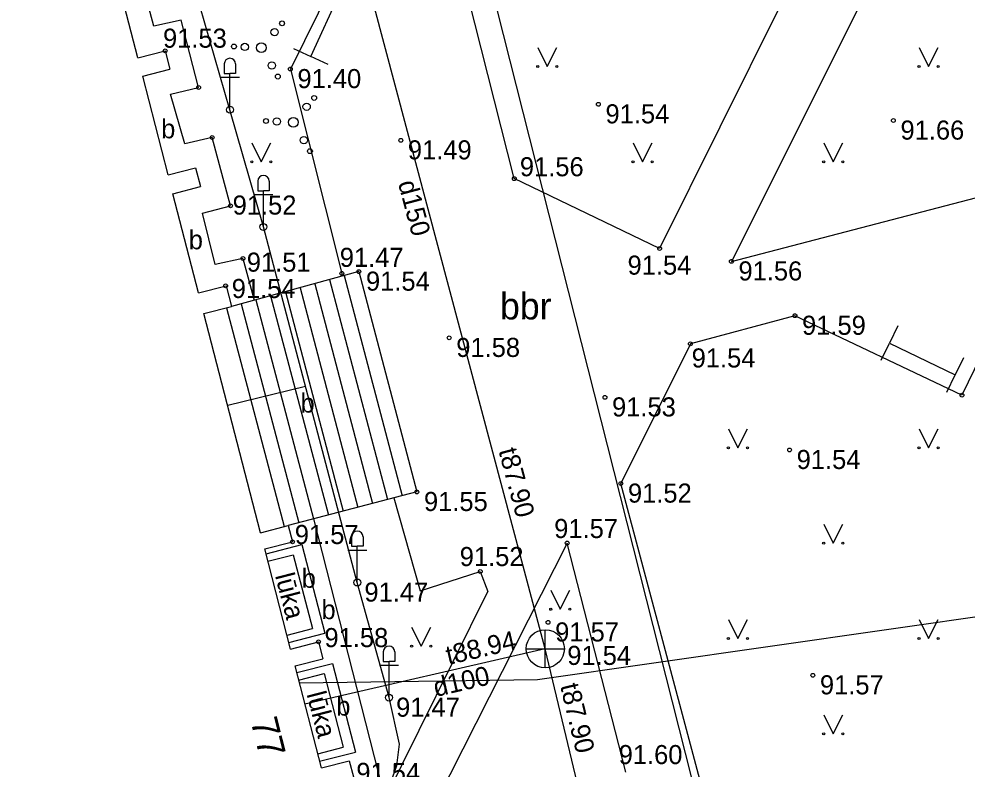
# Model space of a CAD drawing. Extents: x 634272 to 634544, y 247463 to 247653.
# Drawn here: x 634418.64 to 634443.51, y 247569.08 to 247588.75 of the extents above; entities that cross this region are included whole.
import ezdxf

# ---------------------------------------------------------------- set-up
doc = ezdxf.new("R2010")
doc.units = 0
for name, color, linetype in [('APGS_ELEM_####_####_#', 7, 'Continuous'), ('APGS_VADP_ZSPR_####_#', 7, 'Continuous'), ('BUVE_BDET_####_####_#', 7, 'Continuous'), ('BUVE_BDET_####_TKST_#', 7, 'Continuous'), ('BUVE_EKAS_####_####_#', 7, 'Continuous'), ('BUVE_EKAS_ADRS_TKST_#', 7, 'Continuous'), ('BUVE_SOLS_####_####_#', 7, 'Continuous'), ('CELI_CMAL_####_####_#', 7, 'Continuous'), ('CELI_CSEG_####_TKST_#', 7, 'Continuous'), ('RELJ_AATZ_####_TKST_#', 7, 'Continuous'), ('RELJ_ELEM_####_####_#', 7, 'Continuous'), ('ROBZ_UZMR_####_####_#', 7, 'Continuous'), ('SKAN_ELEM_####_####_#', 7, 'Continuous'), ('SKAN_ELEM_PAST_TKST_#', 7, 'Continuous'), ('SKAN_VADP_PAST_####_#', 7, 'Continuous'), ('SKAN_VADP_PAST_TKST_#', 7, 'Continuous'), ('TERT_ELEM_####_####_#', 7, 'Continuous')]:
    doc.layers.add(name, color=color, linetype=linetype)

msp = doc.modelspace()

# ---------------------------------------------------------------- linework, layer by layer
at = {"layer": 'APGS_ELEM_####_####_#'}
for p, q in [((634424.027, 247587.568), (634424.027, 247587.318)), ((634424.327, 247587.568), (634424.327, 247587.318)), ((634423.927, 247587.218), (634424.427, 247587.218)), ((634424.027, 247587.318), (634424.177, 247587.318)), ((634424.177, 247586.368), (634424.177, 247587.318)), ((634424.327, 247587.318), (634424.177, 247587.318)), ((634424.905, 247584.493), (634424.905, 247584.243)), ((634425.205, 247584.493), (634425.205, 247584.243)), ((634424.805, 247584.143), (634425.305, 247584.143)), ((634424.905, 247584.243), (634425.055, 247584.243)), ((634425.055, 247583.293), (634425.055, 247584.243)), ((634425.205, 247584.243), (634425.055, 247584.243)), ((634427.368, 247575.17), (634427.368, 247574.92)), ((634427.668, 247575.17), (634427.668, 247574.92)), ((634427.368, 247574.92), (634427.518, 247574.92)), ((634427.518, 247573.97), (634427.518, 247574.92)), ((634427.668, 247574.92), (634427.518, 247574.92)), ((634427.268, 247574.82), (634427.768, 247574.82)), ((634428.199, 247572.151), (634428.199, 247571.901)), ((634428.499, 247572.151), (634428.499, 247571.901)), ((634428.099, 247571.801), (634428.599, 247571.801)), ((634428.199, 247571.901), (634428.349, 247571.901)), ((634428.349, 247570.951), (634428.349, 247571.901)), ((634428.499, 247571.901), (634428.349, 247571.901))]:
    msp.add_line(p, q, dxfattribs=at)
for centre in [(634424.177, 247586.368), (634425.055, 247583.293), (634427.518, 247573.97), (634428.349, 247570.951)]:
    msp.add_circle(centre, 0.0907, dxfattribs=at)
for centre in [(634424.177, 247587.568), (634425.055, 247584.493), (634427.518, 247575.17), (634428.349, 247572.151)]:
    msp.add_arc(centre, 0.15, 0, 180, dxfattribs=at)
at = {"layer": 'APGS_VADP_ZSPR_####_#'}
for points in [[(634424.64, 247564.493), (634427.489, 247567.387), (634428.243, 247568.282), (634428.556, 247569.174), (634428.62, 247569.734), (634428.349, 247570.951), (634427.518, 247573.97), (634425.055, 247583.293), (634424.177, 247586.368), (634423.255, 247589.552), (634422.487, 247592.599), (634438.755, 247598.02), (634453.341, 247601.325), (634455.217, 247592.645), (634458.049, 247580.186), (634460.842, 247567.679), (634446.181, 247564.209)], [(634426.159, 247579.112), (634424.119, 247578.611)], [(634425.999, 247571.336), (634432.246, 247571.428), (634450.555, 247574.05)]]:
    msp.add_lwpolyline(points, dxfattribs=at)
at = {"layer": 'BUVE_BDET_####_####_#'}
for p, q in [((634426.787, 247581.912), (634428.306, 247576.143)), ((634427.172, 247582.021), (634428.693, 247576.244)), ((634426.016, 247581.701), (634427.532, 247575.941)), ((634426.401, 247581.806), (634427.919, 247576.042)), ((634424.858, 247581.384), (634426.371, 247575.638)), ((634425.244, 247581.49), (634426.758, 247575.739)), ((634425.63, 247581.595), (634427.145, 247575.84)), ((634424.086, 247581.175), (634425.596, 247575.437)), ((634424.472, 247581.279), (634425.984, 247575.537)), ((634426.365, 247575.637), (634428.243, 247568.282)), ((634425.123, 247574.724), (634426.061, 247574.966)), ((634425.174, 247574.527), (634425.839, 247574.699)), ((634425.674, 247572.593), (634426.339, 247572.765)), ((634425.725, 247572.397), (634426.662, 247572.639)), ((634425.928, 247571.608), (634426.866, 247571.85)), ((634425.979, 247571.412), (634426.644, 247571.584)), ((634426.479, 247569.478), (634427.144, 247569.65)), ((634426.53, 247569.281), (634427.467, 247569.523))]:
    msp.add_line(p, q, dxfattribs=at)
for points in [[(634424.519, 247582.466), (634423.79, 247582.308), (634423.459, 247583.653), (634424.19, 247583.849), (634423.711, 247585.639), (634422.99, 247585.469), (634422.619, 247586.777), (634423.356, 247586.952), (634422.897, 247588.72), (634422.18, 247588.555), (634421.828, 247589.872), (634422.546, 247590.02), (634422.083, 247591.821), (634421.394, 247591.641), (634421.036, 247592.981), (634421.77, 247593.16)], [(634424.519, 247582.466), (634424.815, 247581.372)], [(634427.559, 247582.123), (634424.218, 247581.209)], [(634427.559, 247582.123), (634429.08, 247576.345)], [(634429.08, 247576.345), (634425.708, 247575.465)], [(634426.061, 247574.966), (634426.662, 247572.639)], [(634425.839, 247574.699), (634426.339, 247572.765)], [(634426.866, 247571.85), (634427.467, 247569.523)], [(634426.644, 247571.584), (634427.144, 247569.65)]]:
    msp.add_lwpolyline(points, dxfattribs=at)
at = {"layer": 'BUVE_EKAS_####_####_#'}
for p, q in [((634421.763, 247587.727), (634421.085, 247590.354)), ((634421.763, 247587.727), (634422.479, 247587.911)), ((634421.888, 247587.246), (634422.604, 247587.431)), ((634422.555, 247584.662), (634421.888, 247587.246)), ((634422.555, 247584.662), (634423.274, 247584.848)), ((634422.683, 247584.166), (634423.403, 247584.352)), ((634423.355, 247581.566), (634422.683, 247584.166)), ((634423.355, 247581.566), (634424.077, 247581.752)), ((634423.496, 247581.023), (634424.218, 247581.209)), ((634424.98, 247575.277), (634423.496, 247581.023)), ((634424.98, 247575.277), (634425.708, 247575.465)), ((634425.091, 247574.85), (634425.819, 247575.038)), ((634425.769, 247572.224), (634425.091, 247574.85)), ((634425.769, 247572.224), (634426.5, 247572.413)), ((634425.884, 247571.781), (634426.615, 247571.97)), ((634426.574, 247569.109), (634425.884, 247571.781)), ((634426.574, 247569.109), (634427.308, 247569.298))]:
    msp.add_line(p, q, dxfattribs=at)
for points in [[(634422.479, 247587.911), (634422.604, 247587.431)], [(634423.274, 247584.848), (634423.403, 247584.352)], [(634424.077, 247581.752), (634424.218, 247581.209)], [(634425.708, 247575.465), (634425.819, 247575.038)], [(634426.5, 247572.413), (634426.615, 247571.97)], [(634427.308, 247569.298), (634427.419, 247568.871)]]:
    msp.add_lwpolyline(points, dxfattribs=at)
at = {"layer": 'BUVE_SOLS_####_####_#'}
for p, q in [((634425.843, 247587.973), (634426.297, 247587.764)), ((634426.751, 247587.555), (634426.297, 247587.764)), ((634441.697, 247580.697), (634441.479, 247580.247)), ((634441.261, 247579.797), (634441.479, 247580.247)), ((634443.416, 247579.862), (634443.198, 247579.412)), ((634442.98, 247578.962), (634443.198, 247579.412))]:
    msp.add_line(p, q, dxfattribs=at)
for points in [[(634426.297, 247587.764), (634427.081, 247589.469)], [(634441.479, 247580.247), (634443.198, 247579.412)]]:
    msp.add_lwpolyline(points, dxfattribs=at)
at = {"layer": 'CELI_CMAL_####_####_#'}
for points in [[(634422.006, 247600.872), (634425.858, 247601.892), (634428.312, 247592.59), (634425.762, 247587.434), (634427.131, 247582.006)], [(634454.07, 247600.948), (634439.005, 247597.351), (634440.194, 247592.28), (634435.446, 247582.728), (634431.634, 247584.56), (634429.222, 247594.101)], [(634454.416, 247599.108), (634444.542, 247596.807), (634437.329, 247582.391), (634445.746, 247584.585), (634452.082, 247586.129), (634455.906, 247592.579)], [(634458.572, 247580.776), (634457.15, 247581.734), (634452.558, 247584.487), (634445.153, 247582.542), (634443.376, 247578.883), (634438.996, 247580.966), (634436.253, 247580.228), (634434.43, 247576.565)], [(634439.253, 247558.492), (634434.43, 247576.565)], [(634428.478, 247576.188), (634429.169, 247573.753), (634430.743, 247574.259), (634430.939, 247573.736)], [(634433.022, 247575.005), (634424.481, 247558.139), (634424.716, 247557.334)], [(634434.559, 247568.999), (634433.022, 247575.005)], [(634423.98, 247559.871), (634424.815, 247561.591), (634428.243, 247568.282), (634430.939, 247573.736)]]:
    msp.add_lwpolyline(points, dxfattribs=at)
at = {"layer": 'RELJ_ELEM_####_####_#'}
for centre in [(634422.479, 247587.911), (634425.762, 247587.434), (634423.356, 247586.952), (634433.841, 247586.51), (634441.578, 247586.084), (634423.711, 247585.639), (634428.658, 247585.565), (634431.634, 247584.56), (634424.19, 247583.849), (634435.446, 247582.728), (634424.519, 247582.466), (634437.329, 247582.391), (634427.559, 247582.123), (634427.113, 247582.077), (634424.064, 247581.749), (634438.996, 247580.966), (634429.927, 247580.385), (634436.253, 247580.228), (634443.376, 247578.883), (634434.013, 247578.825), (634438.855, 247577.446), (634434.43, 247576.565), (634429.08, 247576.345), (634425.819, 247575.038), (634433.022, 247575.005), (634430.743, 247574.259), (634432.521, 247572.924), (634426.5, 247572.413), (634439.465, 247571.537)]:
    msp.add_circle(centre, 0.05, dxfattribs=at)
at = {"layer": 'ROBZ_UZMR_####_####_#'}
msp.add_lwpolyline([(634428.96, 247597.768), (634439.705, 247555.341)], dxfattribs=at)
at = {"layer": 'SKAN_ELEM_####_####_#'}
for p, q in [((634432.448, 247571.732), (634432.448, 247572.732)), ((634431.948, 247572.232), (634432.948, 247572.232))]:
    msp.add_line(p, q, dxfattribs=at)
msp.add_circle((634432.448, 247572.232), 0.5, dxfattribs=at)
at = {"layer": 'SKAN_VADP_PAST_####_#'}
for points in [[(634467.293, 247556.065), (634460.247, 247556.807), (634435.579, 247559.128), (634432.448, 247572.232), (634426.846, 247593.259), (634423.583, 247606.965), (634413.214, 247604.726), (634403.305, 247602.476), (634405.576, 247593.489), (634409.131, 247581.899)], [(634432.448, 247572.232), (634426.143, 247570.778)]]:
    msp.add_lwpolyline(points, dxfattribs=at)
at = {"layer": 'TERT_ELEM_####_####_#'}
for p, q in [((634432.25, 247588), (634432.5, 247587.5)), ((634432.5, 247587.5), (634432.75, 247588)), ((634442.25, 247588), (634442.5, 247587.5)), ((634442.5, 247587.5), (634442.75, 247588)), ((634424.75, 247585.5), (634425, 247585)), ((634425, 247585), (634425.25, 247585.5)), ((634434.75, 247585.5), (634435, 247585)), ((634435, 247585), (634435.25, 247585.5)), ((634439.75, 247585.5), (634440, 247585)), ((634440, 247585), (634440.25, 247585.5)), ((634437.25, 247578), (634437.5, 247577.5)), ((634437.5, 247577.5), (634437.75, 247578)), ((634442.25, 247578), (634442.5, 247577.5)), ((634442.5, 247577.5), (634442.75, 247578)), ((634439.75, 247575.5), (634440, 247575)), ((634440, 247575), (634440.25, 247575.5)), ((634432.592, 247573.77), (634432.842, 247573.27)), ((634432.842, 247573.27), (634433.092, 247573.77)), ((634437.25, 247573), (634437.5, 247572.5)), ((634437.5, 247572.5), (634437.75, 247573)), ((634442.25, 247573), (634442.5, 247572.5)), ((634442.5, 247572.5), (634442.75, 247573)), ((634428.943, 247572.802), (634429.193, 247572.302)), ((634429.193, 247572.302), (634429.443, 247572.802)), ((634439.75, 247570.5), (634440, 247570)), ((634440, 247570), (634440.25, 247570.5))]:
    msp.add_line(p, q, dxfattribs=at)
for centre, radius in [((634425.544, 247588.632), 0.064), ((634425.348, 247588.401), 0.096), ((634424.566, 247588.014), 0.096), ((634425, 247587.993), 0.128), ((634424.282, 247588.027), 0.064), ((634425.276, 247587.526), 0.096), ((634432.25, 247587.5), 0.028), ((634432.75, 247587.5), 0.0263), ((634442.25, 247587.5), 0.028), ((634442.75, 247587.5), 0.0263), ((634425.434, 247587.237), 0.064), ((634426.385, 247586.677), 0.064), ((634426.189, 247586.446), 0.096), ((634425.123, 247586.072), 0.064), ((634425.407, 247586.059), 0.096), ((634425.841, 247586.038), 0.128), ((634426.117, 247585.571), 0.096), ((634426.275, 247585.282), 0.064), ((634424.75, 247585), 0.028), ((634425.25, 247585), 0.0263), ((634434.75, 247585), 0.028), ((634435.25, 247585), 0.0263), ((634439.75, 247585), 0.028), ((634440.25, 247585), 0.0263), ((634437.25, 247577.5), 0.028), ((634437.75, 247577.5), 0.0263), ((634442.25, 247577.5), 0.028), ((634442.75, 247577.5), 0.0263), ((634439.75, 247575), 0.028), ((634440.25, 247575), 0.0263), ((634432.591, 247573.269), 0.028), ((634433.091, 247573.269), 0.0263), ((634437.25, 247572.5), 0.028), ((634437.75, 247572.5), 0.0263), ((634442.25, 247572.5), 0.028), ((634442.75, 247572.5), 0.0263), ((634428.943, 247572.301), 0.028), ((634429.443, 247572.301), 0.0263), ((634439.75, 247570), 0.028), ((634440.25, 247570), 0.0263)]:
    msp.add_circle(centre, radius, dxfattribs=at)

# ---------------------------------------------------------------- texts
at = {"layer": 'BUVE_BDET_####_TKST_#'}
for p in [(634422.373, 247585.618), (634423.097, 247582.708), (634426.028, 247578.426), (634426.059, 247573.831), (634426.578, 247573.009), (634426.965, 247570.48)]:
    msp.add_text('b', height=0.5, dxfattribs=at).set_placement(p)
for p in [(634425.358, 247574.153), (634426.185, 247571.046)]:
    msp.add_text('lūka', height=0.5, rotation=284.4886, dxfattribs=at).set_placement(p)
at = {"layer": 'BUVE_EKAS_ADRS_TKST_#'}
msp.add_text('77', height=0.7, rotation=284.1272, dxfattribs=at).set_placement((634424.715, 247570.342))
at = {"layer": 'CELI_CSEG_####_TKST_#'}
msp.add_text('bbr', height=0.7, dxfattribs=at).set_placement((634431.259, 247580.869))
at = {"layer": 'RELJ_AATZ_####_TKST_#'}
for s, p in [(' 91.53', (634422.236, 247587.994)), (' 91.40', (634425.762, 247586.934)), (' 91.54', (634433.841, 247586.01)), (' 91.66', (634441.578, 247585.584)), (' 91.49', (634428.658, 247585.065)), (' 91.56', (634431.596, 247584.623)), (' 91.52', (634424.062, 247583.618)), (' 91.51', (634424.433, 247582.121)), (' 91.47', (634426.872, 247582.247)), (' 91.54', (634434.42, 247582.043)), (' 91.56', (634437.329, 247581.891)), (' 91.54', (634427.559, 247581.623)), (' 91.54', (634424.038, 247581.43)), (' 91.59', (634438.996, 247580.466)), (' 91.58', (634429.927, 247579.885)), (' 91.54', (634436.101, 247579.609)), (' 91.53', (634434.013, 247578.325)), (' 91.54', (634438.855, 247576.946)), (' 91.52', (634434.43, 247576.065)), (' 91.55', (634429.08, 247575.845)), (' 91.57', (634425.692, 247574.979)), (' 91.57', (634432.496, 247575.136)), (' 91.52', (634430.018, 247574.401)), (' 91.47', (634427.518, 247573.47)), (' 91.57', (634432.521, 247572.424)), (' 91.58', (634426.47, 247572.276)), (' 91.57', (634439.465, 247571.037)), (' 91.47', (634428.349, 247570.451)), (' 91.60', (634434.187, 247569.208)), (' 91.54', (634427.306, 247568.741))]:
    msp.add_text(s, height=0.5, dxfattribs=at).set_placement(p)
at = {"layer": 'SKAN_ELEM_PAST_TKST_#'}
msp.add_text(' 91.54', height=0.5, dxfattribs=at).set_placement((634432.839, 247571.809))
at = {"layer": 'SKAN_VADP_PAST_TKST_#'}
for s, rotation, p in [('d150', 284.9182, (634428.582, 247584.448)), ('t87.90', 284.9182, (634431.218, 247577.43)), ('t88.94', 12.9851, (634429.907, 247571.809)), ('d100', 12.9851, (634429.578, 247570.969)), ('t87.90', 283.438, (634432.835, 247571.265))]:
    msp.add_text(s, height=0.5, rotation=rotation, dxfattribs=at).set_placement(p)

doc.saveas('drawing.dxf')
